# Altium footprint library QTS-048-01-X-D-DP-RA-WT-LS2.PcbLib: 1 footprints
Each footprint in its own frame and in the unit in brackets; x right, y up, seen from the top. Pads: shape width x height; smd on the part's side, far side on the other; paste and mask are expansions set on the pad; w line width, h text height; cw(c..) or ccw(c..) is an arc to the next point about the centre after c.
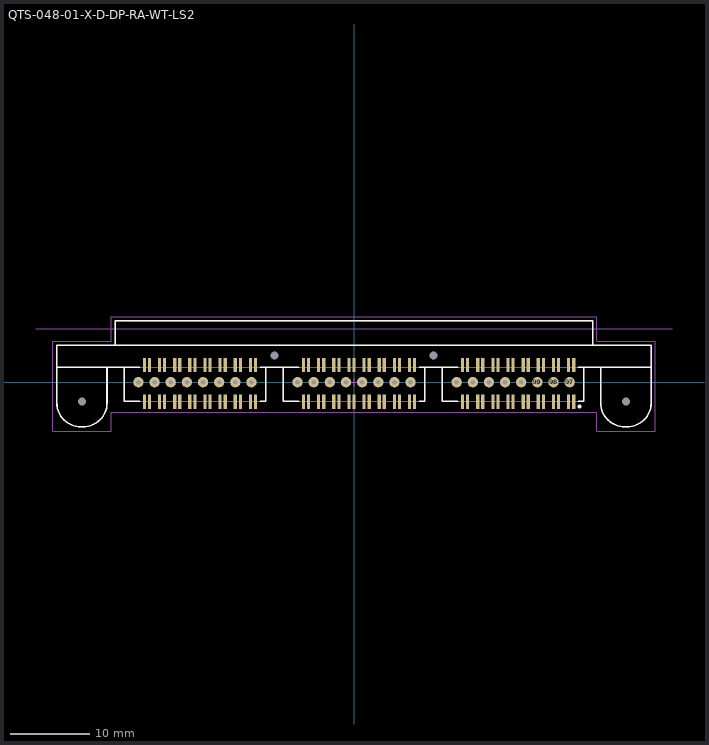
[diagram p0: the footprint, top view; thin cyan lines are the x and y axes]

## QTS-048-01-X-D-DP-RA-WT-LS2 [mm] "0.635mm pitch, 48 pin, terminal strip; r/a, double row"
height 9.42
pads (124):
  rect 0.4x1.8 smd mask+0: 1(27.621,-2.45) 2(27.621,2.16) 3(26.982,-2.45) 4(26.982,2.16) 5(25.716,-2.45) 6(25.716,2.16) 7(25.077,-2.45) 8(25.077,2.16) 9(23.811,-2.45) 10(23.811,2.16) 11(23.172,-2.45) 12(23.172,2.16) 13(21.906,-2.45) 14(21.906,2.16) 15(21.267,-2.45) 16(21.267,2.16) 17(20.001,-2.45) 18(20.001,2.16) 19(19.362,-2.45) 20(19.362,2.16) 21(18.096,-2.45) 22(18.096,2.16) 23(17.457,-2.45) 24(17.457,2.16) 25(16.191,-2.45) 26(16.191,2.16) 27(15.552,-2.45) 28(15.552,2.16) 29(14.286,-2.45) 30(14.286,2.16) 31(13.647,-2.45) 32(13.647,2.16) 33(7.622,-2.45) 34(7.622,2.16) 35(6.981,-2.45) 36(6.981,2.16) 37(5.717,-2.45) 38(5.717,2.16) 39(5.076,-2.45) 40(5.076,2.16) 41(3.812,-2.45) 42(3.812,2.16) 43(3.171,-2.45) 44(3.171,2.16) 45(1.907,-2.45) 46(1.907,2.16) 47(1.266,-2.45) 48(1.266,2.16) 49(0.002,-2.45) 50(0.002,2.16) 51(-0.639,-2.45) 52(-0.639,2.16) 53(-1.903,-2.45) 54(-1.903,2.16) 55(-2.544,-2.45) 56(-2.544,2.16) 57(-3.808,-2.45) 58(-3.808,2.16) 59(-4.449,-2.45) 60(-4.449,2.16) 61(-5.713,-2.45) 62(-5.713,2.16) 63(-6.354,-2.45) 64(-6.354,2.16) 65(-12.378,-2.45) 66(-12.378,2.16) 67(-13.019,-2.45) 68(-13.019,2.16) 69(-14.283,-2.45) 70(-14.283,2.16) 71(-14.924,-2.45) 72(-14.924,2.16) 73(-16.188,-2.45) 74(-16.188,2.16) 75(-16.829,-2.45) 76(-16.829,2.16) 77(-18.093,-2.45) 78(-18.093,2.16) 79(-18.734,-2.45) 80(-18.734,2.16) 81(-19.998,-2.45) 82(-19.998,2.16) 83(-20.639,-2.45) 84(-20.639,2.16) 85(-21.903,-2.45) 86(-21.903,2.16) 87(-22.544,-2.45) 88(-22.544,2.16) 89(-23.808,-2.45) 90(-23.808,2.16) 91(-24.449,-2.45) 92(-24.449,2.16) 93(-25.713,-2.45) 94(-25.713,2.16) 95(-26.354,-2.45) 96(-26.354,2.16)
  round 1.3 hole 0.6 mask+0: 97(27.112,0) 98(25.081,0) 99(23.052,0) 100(21.021,0) 101(18.992,0) 102(16.962,0) 103(14.931,0) 104(12.902,0) 105(7.111,0) 106(5.082,0) 107(3.052,0) 108(1.021,0) 109(-1.008,0) 110(-3.039,0) 111(-5.068,0) 112(-7.098,0) 113(-12.889,0) 114(-14.918,0) 115(-16.949,0) 116(-18.978,0) 117(-21.009,0) 118(-23.039,0) 119(-25.068,0) 120(-27.099,0)
  round 0.5 hole 1 unplated mask+0: 121(10,3.35) 122(-10,3.35) 123(34.191,-2.45) 124(-34.198,-2.45)
Top Overlay:
  circle w0.25: c28.35,-3.05 r0.125
  lines w0.2: -37.35,-2.625 -37.35,1.86 ; -37.35,-2.624 ccw(c-34.374,-2.624) -34.374,-5.6 ; -34.372,-5.6 -34.022,-5.6 ; -34.024,-5.6 ccw(c-34.024,-2.626) -31.05,-2.626 ; -31.05,-2.625 -31.05,1.85 ; -30,4.65 -30,7.7 30,7.7 30,4.65 ; -28.9,1.85 -28.9,-2.4 -26.95,-2.4 ; -26.95,1.85 -37.35,1.85 -37.35,4.65 37.35,4.65 37.35,1.85 ; -11.8,-2.4 -11.1,-2.4 -11.1,1.85 ; -11.8,1.85 -6.95,1.85 ; -8.9,1.85 -8.9,-2.4 -6.95,-2.4 ; 8.2,-2.4 8.9,-2.4 8.9,1.85 ; 8.2,1.85 13.05,1.85 ; 11.1,1.85 11.1,-2.4 13.05,-2.4 ; 28.2,-2.4 28.9,-2.4 28.9,1.85 ; 28.2,1.85 37.35,1.85 ; 31,1.85 31,-2.625 ccw(c33.996,-2.604) 34.017,-5.6 34.366,-5.6 ccw(c34.366,-2.616) 37.35,-2.627 ; 37.35,-2.625 37.35,1.85
Mechanical 12:
  lines w0.001: -40,6.69 40,6.69
Mechanical 13:
  lines w0.1: -37.35,-2.625 -37.35,1.86 ; -37.35,-2.624 ccw(c-34.374,-2.624) -34.374,-5.6 ; -34.372,-5.6 -34.022,-5.6 ; -34.024,-5.6 ccw(c-34.024,-2.626) -31.05,-2.626 ; -31.05,-2.625 -31.05,1.85 ; -30,4.65 -30,7.7 30,7.7 30,4.65 ; -28.9,1.85 -28.9,-2.4 -11.1,-2.4 -11.1,1.85 ; -8.9,1.85 -8.9,-2.4 8.9,-2.4 8.9,1.85 ; 11.1,1.85 11.1,-2.4 28.9,-2.4 28.9,1.85 ; 31,1.85 31,-2.625 ccw(c33.996,-2.604) 34.017,-5.6 34.366,-5.6 ccw(c34.366,-2.616) 37.35,-2.627 ; 37.35,-2.625 37.35,1.85 ; 37.35,1.85 37.35,4.65 -37.35,4.65 -37.35,1.85 37.35,1.85
  text ".Designator" at 0,0 h1.52
Mechanical 15:
  lines w0.05: -0.5,0 0.5,0 ; 0,-0.5 0,0.5 ; -37.85,-6.15 -30.5,-6.15 -30.5,-3.8 30.5,-3.8 30.5,-6.15 37.85,-6.15 37.85,5.15 30.5,5.15 30.5,8.2 -30.5,8.2 -30.5,5.15 -37.85,5.15 -37.85,-6.15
